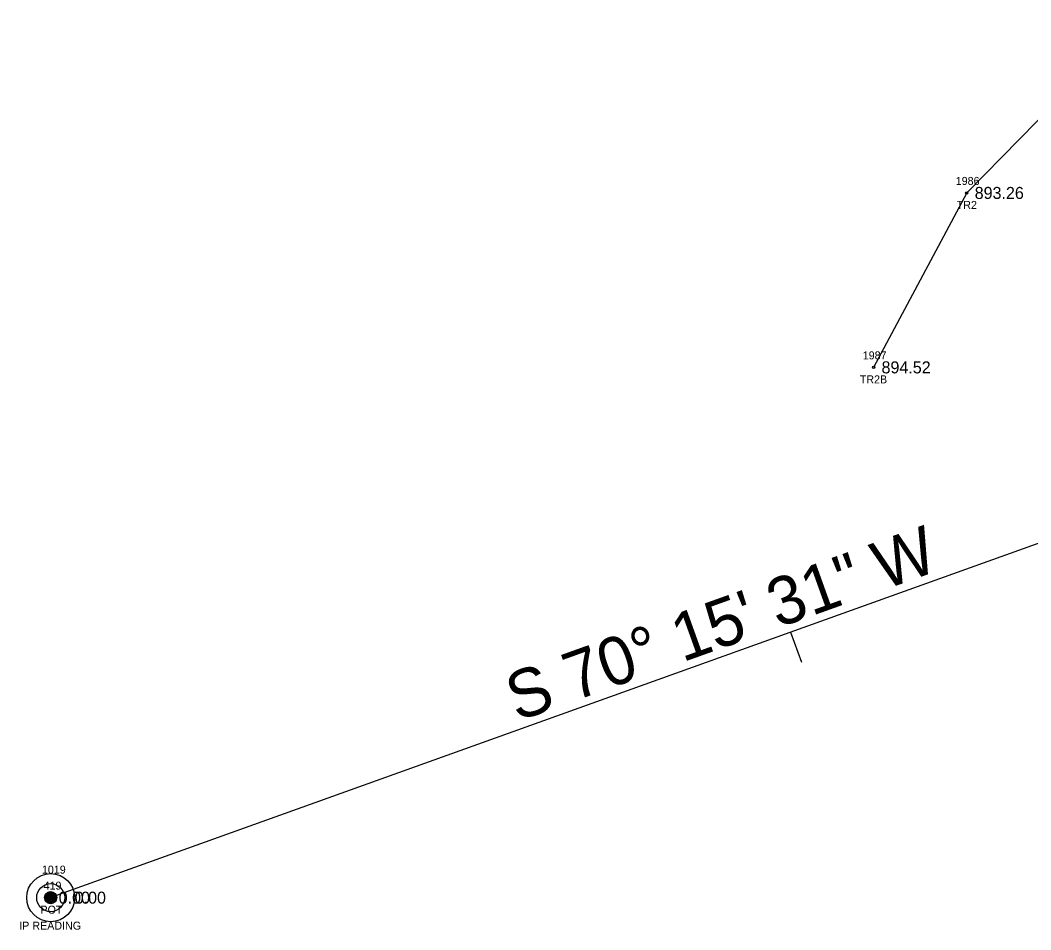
# Model space of a CAD drawing. Extents: x 1448136 to 1453623, y 1125056 to 1128842.
# Drawn here: x 1448759.2 to 1448885.5, y 1126834.5 to 1126948.2 of the extents above; entities that cross this region are included whole.
import ezdxf

# ---------------------------------------------------------------- set-up
doc = ezdxf.new("R2010")
doc.units = 0
for name, color, linetype in [('RD_EX_DV_Prop_txCode', 7, 'Continuous'), ('RD_EX_DV_PropPin', 7, 'Continuous'), ('RD_EX_TX_DV_Prop_ELEV', 7, 'Continuous'), ('RD_EX_TX_VEG_ELEV', 7, 'Continuous'), ('RD_EX_VEG', 7, 'Continuous'), ('RD_EX_VEG_txCode', 7, 'Continuous'), ('RD_HC_Cl', 7, 'Continuous'), ('RD_HC_Data', 7, 'Continuous'), ('RD_HC_Data_Tic', 7, 'Continuous'), ('RD_HC_Survey_ELEV', 7, 'Continuous'), ('RD_HC_txCode', 7, 'Continuous'), ('RD_SMD_Locator', 7, 'Continuous')]:
    doc.layers.add(name, color=color, linetype=linetype)

msp = doc.modelspace()

# ---------------------------------------------------------------- linework, layer by layer
at = {"layer": 'RD_EX_DV_PropPin'}
for p, q in [((1448762.51, 1126838), (1448762.51, 1126839.1)), ((1448762.54, 1126837.97), (1448762.54, 1126839.13)), ((1448762.58, 1126837.94), (1448762.58, 1126839.16)), ((1448762.61, 1126837.92), (1448762.61, 1126839.18)), ((1448762.65, 1126837.89), (1448762.65, 1126839.21)), ((1448762.68, 1126837.87), (1448762.68, 1126839.23)), ((1448762.72, 1126837.86), (1448762.72, 1126839.24)), ((1448762.75, 1126837.84), (1448762.75, 1126839.26)), ((1448762.79, 1126837.83), (1448762.79, 1126839.27)), ((1448762.82, 1126837.82), (1448762.82, 1126839.28)), ((1448762.86, 1126837.81), (1448762.86, 1126839.29)), ((1448762.89, 1126837.8), (1448762.89, 1126839.3)), ((1448762.93, 1126837.8), (1448762.93, 1126839.3)), ((1448762.96, 1126837.79), (1448762.96, 1126839.31)), ((1448763, 1126837.79), (1448763, 1126839.31)), ((1448763.03, 1126837.79), (1448763.03, 1126839.31)), ((1448763.07, 1126837.79), (1448763.07, 1126839.31)), ((1448763.1, 1126837.79), (1448763.1, 1126839.31)), ((1448763.14, 1126837.8), (1448763.14, 1126839.3)), ((1448763.17, 1126837.8), (1448763.17, 1126839.3)), ((1448763.21, 1126837.81), (1448763.21, 1126839.29)), ((1448763.24, 1126837.82), (1448763.24, 1126839.28)), ((1448763.28, 1126837.83), (1448763.28, 1126839.27)), ((1448763.31, 1126837.84), (1448763.31, 1126839.26)), ((1448763.35, 1126837.86), (1448763.35, 1126839.24)), ((1448763.38, 1126837.87), (1448763.38, 1126839.23)), ((1448763.42, 1126837.89), (1448763.42, 1126839.21)), ((1448763.45, 1126837.92), (1448763.45, 1126839.18)), ((1448763.49, 1126837.94), (1448763.49, 1126839.16)), ((1448763.52, 1126837.97), (1448763.52, 1126839.13)), ((1448763.56, 1126838), (1448763.56, 1126839.1)), ((1448762.3, 1126838.35), (1448762.3, 1126838.75)), ((1448762.33, 1126838.25), (1448762.33, 1126838.85)), ((1448762.37, 1126838.18), (1448762.37, 1126838.92)), ((1448762.4, 1126838.12), (1448762.4, 1126838.98)), ((1448762.44, 1126838.08), (1448762.44, 1126839.02)), ((1448762.47, 1126838.03), (1448762.47, 1126839.06)), ((1448763.59, 1126838.03), (1448763.59, 1126839.06)), ((1448763.63, 1126838.08), (1448763.63, 1126839.02)), ((1448763.66, 1126838.12), (1448763.66, 1126838.98)), ((1448763.7, 1126838.18), (1448763.7, 1126838.92)), ((1448763.73, 1126838.25), (1448763.73, 1126838.85)), ((1448763.77, 1126838.35), (1448763.77, 1126838.75))]:
    msp.add_line(p, q, dxfattribs=at)
for radius in [1.75, 0.761]:
    msp.add_circle((1448763.03, 1126838.55), radius, dxfattribs=at)
at = {"layer": 'RD_EX_VEG'}
msp.add_lwpolyline([(1448868.01, 1126973.97), (1448895.01, 1126944.46), (1448877.49, 1126926.62), (1448865.85, 1126904.82)], dxfattribs=at)
at = {"layer": 'RD_HC_Cl'}
msp.add_line((1448931, 1126898.83), (1448763.03, 1126838.55), dxfattribs=at)
at = {"layer": 'RD_HC_Data'}
for radius in [3, 0.282]:
    msp.add_circle((1448763.03, 1126838.55), radius, dxfattribs=at)
at = {"layer": 'RD_HC_Data_Tic'}
msp.add_line((1448855.49, 1126871.73), (1448856.84, 1126867.96), dxfattribs=at)
at = {"layer": 'RD_SMD_Locator'}
for centre in [(1448877.49, 1126926.62), (1448865.85, 1126904.82), (1448763.03, 1126838.55), (1448763.03, 1126838.55)]:
    msp.add_circle(centre, 0.15, dxfattribs=at)

# ---------------------------------------------------------------- texts
at = {"layer": 'RD_EX_DV_Prop_txCode'}
for s, p in [('1019', (1448761.93, 1126841.55)), ('IP READING', (1448759.1, 1126834.55))]:
    msp.add_text(s, height=1, dxfattribs=at).set_placement(p)
at = {"layer": 'RD_EX_TX_DV_Prop_ELEV'}
msp.add_text('0.00', height=1.5, dxfattribs=at).set_placement((1448766.03, 1126837.8))
at = {"layer": 'RD_EX_TX_VEG_ELEV'}
for s, p in [('893.26', (1448878.49, 1126925.87)), ('894.52', (1448866.85, 1126904.07))]:
    msp.add_text(s, height=1.5, dxfattribs=at).set_placement(p)
at = {"layer": 'RD_EX_VEG_txCode'}
for s, p in [('1986', (1448876.12, 1126927.62)), ('TR2', (1448876.24, 1126924.62)), ('1987', (1448864.5, 1126905.82)), ('TR2B', (1448864.13, 1126902.82))]:
    msp.add_text(s, height=1, dxfattribs=at).set_placement(p)
at = {"layer": 'RD_HC_Data'}
msp.add_text('S 70%%d 15\' 31" W', height=6, rotation=19.7413, dxfattribs=at).set_placement((1448821.31, 1126860.53))
at = {"layer": 'RD_HC_Survey_ELEV'}
msp.add_text('0.00', height=1.5, dxfattribs=at).set_placement((1448764.03, 1126837.8))
at = {"layer": 'RD_HC_txCode'}
for s, p in [('419', (1448762.14, 1126839.55)), ('POT', (1448761.75, 1126836.55))]:
    msp.add_text(s, height=1, dxfattribs=at).set_placement(p)

doc.saveas('drawing.dxf')
